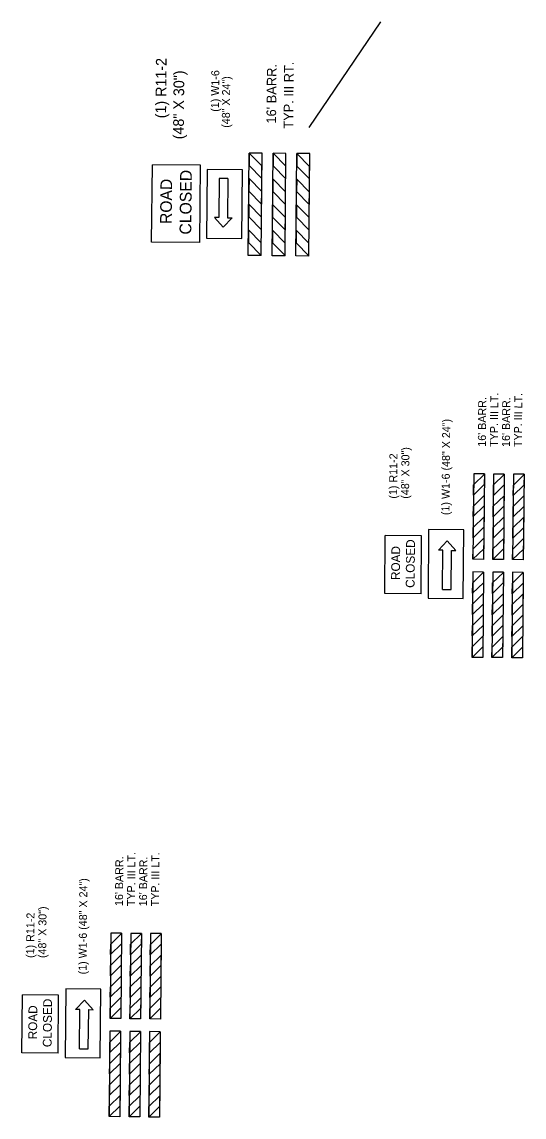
# Model space of a CAD drawing. Extents: x 1770269 to 1771406, y 724066 to 730989.
# Drawn here: x 1771030 to 1771406, y 727534 to 728355 of the extents above; entities that cross this region are included whole.
import ezdxf

# ---------------------------------------------------------------- set-up
doc = ezdxf.new("R2010")
doc.units = 0
doc.layers.add('R_Border PE', color=7, linetype='Continuous')
doc.layers.add('R_MOT', color=7, linetype='Continuous')

msp = doc.modelspace()

# ---------------------------------------------------------------- linework, layer by layer
at = {"layer": 'R_Border PE'}
msp.add_line((1771245.26, 728275.64), (1771299.11, 728354.86), dxfattribs=at)
at = {"layer": 'R_MOT'}
for p, q in [((1771199.65, 728179.7), (1771200.35, 728256.57)), ((1771210, 728256.49), (1771200.35, 728256.57)), ((1771209.3, 728179.61), (1771210, 728256.49)), ((1771209.97, 728256.43), (1771209.91, 728256.49)), ((1771217.54, 728179.54), (1771218.24, 728256.41)), ((1771227.86, 728256.32), (1771218.24, 728256.41)), ((1771227.86, 728256.32), (1771218.24, 728256.41)), ((1771227.16, 728179.45), (1771227.86, 728256.32)), ((1771235.38, 728179.37), (1771236.07, 728256.25)), ((1771245.7, 728256.16), (1771236.07, 728256.25)), ((1771245, 728179.29), (1771245.7, 728256.16)), ((1771127.17, 728189.81), (1771127.7, 728247.78)), ((1771163.91, 728247.45), (1771127.7, 728247.78)), ((1771163.38, 728189.49), (1771163.91, 728247.45)), ((1771177.86, 728237.53), (1771177.59, 728208.15)), ((1771184.4, 728237.47), (1771177.86, 728237.53)), ((1771184.4, 728237.47), (1771184.14, 728208.09)), ((1771177.59, 728208.15), (1771174.32, 728208.18)), ((1771180.8, 728200.94), (1771174.32, 728208.18)), ((1771187.41, 728208.06), (1771180.8, 728200.94)), ((1771184.14, 728208.09), (1771187.41, 728208.06)), ((1771163.38, 728189.49), (1771127.17, 728189.81)), ((1771209.3, 728179.61), (1771199.65, 728179.7)), ((1771227.16, 728179.45), (1771217.54, 728179.54)), ((1771245, 728179.29), (1771235.38, 728179.37)), ((1771368.62, 728016.03), (1771368.04, 727952)), ((1771376.66, 728015.96), (1771368.62, 728016.03)), ((1771376.66, 728015.96), (1771376.08, 727951.93)), ((1771383.53, 728015.9), (1771382.94, 727951.87)), ((1771391.54, 728015.82), (1771383.53, 728015.9)), ((1771391.54, 728015.82), (1771390.96, 727951.79)), ((1771398.38, 728015.76), (1771397.8, 727951.73)), ((1771406.4, 728015.69), (1771398.38, 728015.76)), ((1771406.4, 728015.69), (1771405.82, 727951.66)), ((1771301.97, 727926.34), (1771302.36, 727969.8)), ((1771329.5, 727969.55), (1771302.36, 727969.8)), ((1771329.11, 727926.1), (1771329.5, 727969.55)), ((1771342.2, 727958.76), (1771348.81, 727965.88)), ((1771348.81, 727965.88), (1771355.29, 727958.65)), ((1771345.48, 727958.74), (1771342.2, 727958.76)), ((1771345.21, 727929.35), (1771345.48, 727958.74)), ((1771351.75, 727929.29), (1771352.02, 727958.68)), ((1771352.02, 727958.68), (1771355.29, 727958.65)), ((1771376.08, 727951.93), (1771368.04, 727952)), ((1771376.06, 727951.98), (1771376.01, 727951.93)), ((1771390.96, 727951.79), (1771382.94, 727951.87)), ((1771390.96, 727951.79), (1771382.94, 727951.87)), ((1771405.82, 727951.66), (1771397.8, 727951.73)), ((1771367.96, 727942.5), (1771367.37, 727878.47)), ((1771375.99, 727942.43), (1771367.96, 727942.5)), ((1771375.99, 727942.43), (1771375.41, 727878.4)), ((1771382.86, 727942.37), (1771382.28, 727878.34)), ((1771390.87, 727942.3), (1771382.86, 727942.37)), ((1771390.87, 727942.3), (1771390.29, 727878.27)), ((1771397.71, 727942.23), (1771397.13, 727878.2)), ((1771405.73, 727942.16), (1771397.71, 727942.23)), ((1771405.73, 727942.16), (1771405.15, 727878.13)), ((1771329.11, 727926.1), (1771301.97, 727926.34)), ((1771345.21, 727929.35), (1771351.75, 727929.29)), ((1771375.41, 727878.4), (1771367.37, 727878.47)), ((1771375.39, 727878.45), (1771375.34, 727878.4)), ((1771390.29, 727878.27), (1771382.28, 727878.34)), ((1771390.29, 727878.27), (1771382.28, 727878.34)), ((1771405.15, 727878.13), (1771397.13, 727878.2)), ((1771096.55, 727671.69), (1771095.97, 727607.66)), ((1771104.59, 727671.62), (1771096.55, 727671.69)), ((1771104.59, 727671.62), (1771104.01, 727607.59)), ((1771111.45, 727671.55), (1771110.87, 727607.52)), ((1771119.47, 727671.48), (1771111.45, 727671.55)), ((1771119.47, 727671.48), (1771118.89, 727607.45)), ((1771126.31, 727671.42), (1771125.73, 727607.39)), ((1771134.32, 727671.35), (1771126.31, 727671.42)), ((1771134.32, 727671.35), (1771133.74, 727607.32)), ((1771029.89, 727582), (1771030.29, 727625.45)), ((1771057.43, 727625.21), (1771030.29, 727625.45)), ((1771057.03, 727581.76), (1771057.43, 727625.21)), ((1771070.13, 727614.42), (1771076.74, 727621.54)), ((1771076.74, 727621.54), (1771083.22, 727614.3)), ((1771073.4, 727614.39), (1771070.13, 727614.42)), ((1771073.13, 727585.01), (1771073.4, 727614.39)), ((1771079.68, 727584.95), (1771079.95, 727614.33)), ((1771079.95, 727614.33), (1771083.22, 727614.3)), ((1771104.01, 727607.59), (1771095.97, 727607.66)), ((1771103.98, 727607.63), (1771103.94, 727607.59)), ((1771118.89, 727607.45), (1771110.87, 727607.52)), ((1771118.89, 727607.45), (1771110.87, 727607.52)), ((1771133.74, 727607.32), (1771125.73, 727607.39)), ((1771095.88, 727598.16), (1771095.3, 727534.13)), ((1771103.92, 727598.09), (1771095.88, 727598.16)), ((1771103.92, 727598.09), (1771103.34, 727534.06)), ((1771110.78, 727598.03), (1771110.2, 727534)), ((1771118.8, 727597.95), (1771110.78, 727598.03)), ((1771118.8, 727597.95), (1771118.22, 727533.92)), ((1771125.64, 727597.89), (1771125.06, 727533.86)), ((1771133.66, 727597.82), (1771125.64, 727597.89)), ((1771133.66, 727597.82), (1771133.07, 727533.79)), ((1771057.03, 727581.76), (1771029.89, 727582)), ((1771073.13, 727585.01), (1771079.68, 727584.95)), ((1771103.34, 727534.06), (1771095.3, 727534.13)), ((1771103.32, 727534.11), (1771103.27, 727534.06)), ((1771118.22, 727533.92), (1771110.2, 727534)), ((1771118.22, 727533.92), (1771110.2, 727534)), ((1771133.07, 727533.79), (1771125.06, 727533.86))]:
    msp.add_line(p, q, dxfattribs=at)
for points in [[(1771200.35, 728256.57), (1771200.29, 728247.12), (1771209.8, 728237.44), (1771209.88, 728246.86)], [(1771218.24, 728256.41), (1771218.18, 728246.96), (1771227.69, 728237.28), (1771227.78, 728246.7)], [(1771236.07, 728256.25), (1771236.02, 728246.8), (1771245.52, 728237.12), (1771245.61, 728246.54)], [(1771194.76, 728192.42), (1771195.23, 728243.95), (1771168.88, 728244.19), (1771168.41, 728192.66)], [(1771200.17, 728237.36), (1771200.11, 728227.91), (1771209.62, 728218.23), (1771209.71, 728227.65)], [(1771218.06, 728237.2), (1771218.01, 728227.75), (1771227.52, 728218.07), (1771227.6, 728227.49)], [(1771235.9, 728237.04), (1771235.84, 728227.59), (1771245.35, 728217.91), (1771245.44, 728227.33)], [(1771200, 728218.16), (1771199.94, 728208.7), (1771209.45, 728199.02), (1771209.53, 728208.44)], [(1771217.89, 728217.99), (1771217.83, 728208.54), (1771227.34, 728198.86), (1771227.43, 728208.28)], [(1771235.73, 728217.83), (1771235.67, 728208.38), (1771245.18, 728198.7), (1771245.26, 728208.12)], [(1771199.82, 728198.95), (1771199.77, 728189.5), (1771209.27, 728179.81), (1771209.36, 728189.24)], [(1771217.72, 728198.78), (1771217.66, 728189.33), (1771227.17, 728179.65), (1771227.25, 728189.07)], [(1771235.55, 728198.62), (1771235.49, 728189.17), (1771245, 728179.49), (1771245.09, 728188.91)], [(1771368.48, 728000), (1771368.57, 728007.87), (1771376.64, 728015.79), (1771376.57, 728007.94)], [(1771383.38, 727999.86), (1771383.48, 728007.74), (1771391.54, 728015.66), (1771391.47, 728007.81)], [(1771398.24, 727999.73), (1771398.33, 728007.6), (1771406.4, 728015.52), (1771406.32, 728007.67)], [(1771368.33, 727984), (1771368.43, 727991.87), (1771376.49, 727999.79), (1771376.42, 727991.94)], [(1771383.24, 727983.87), (1771383.33, 727991.74), (1771391.4, 727999.66), (1771391.32, 727991.81)], [(1771398.09, 727983.73), (1771398.19, 727991.6), (1771406.25, 727999.52), (1771406.18, 727991.67)], [(1771368.19, 727968), (1771368.28, 727975.87), (1771376.35, 727983.79), (1771376.28, 727975.94)], [(1771383.09, 727967.87), (1771383.19, 727975.74), (1771391.25, 727983.66), (1771391.18, 727975.81)], [(1771397.95, 727967.73), (1771398.04, 727975.6), (1771406.11, 727983.52), (1771406.03, 727975.67)], [(1771334.85, 727974.41), (1771334.38, 727922.88), (1771360.73, 727922.64), (1771361.2, 727974.17)], [(1771368.04, 727952), (1771368.14, 727959.87), (1771376.2, 727967.79), (1771376.13, 727959.94)], [(1771382.94, 727951.87), (1771383.04, 727959.74), (1771391.1, 727967.66), (1771391.03, 727959.81)], [(1771397.8, 727951.73), (1771397.9, 727959.6), (1771405.96, 727967.52), (1771405.89, 727959.67)], [(1771367.81, 727926.47), (1771367.91, 727934.34), (1771375.97, 727942.26), (1771375.9, 727934.42)], [(1771382.71, 727926.34), (1771382.81, 727934.21), (1771390.87, 727942.13), (1771390.8, 727934.28)], [(1771397.57, 727926.2), (1771397.66, 727934.07), (1771405.73, 727941.99), (1771405.66, 727934.15)], [(1771367.66, 727910.47), (1771367.76, 727918.34), (1771375.82, 727926.26), (1771375.75, 727918.42)], [(1771382.57, 727910.34), (1771382.66, 727918.21), (1771390.73, 727926.13), (1771390.66, 727918.28)], [(1771397.42, 727910.2), (1771397.52, 727918.07), (1771405.58, 727925.99), (1771405.51, 727918.15)], [(1771367.52, 727894.47), (1771367.61, 727902.35), (1771375.68, 727910.26), (1771375.61, 727902.42)], [(1771382.42, 727894.34), (1771382.52, 727902.21), (1771390.58, 727910.13), (1771390.51, 727902.28)], [(1771397.28, 727894.2), (1771397.37, 727902.07), (1771405.44, 727909.99), (1771405.37, 727902.15)], [(1771367.37, 727878.47), (1771367.47, 727886.35), (1771375.53, 727894.26), (1771375.46, 727886.42)], [(1771382.28, 727878.34), (1771382.37, 727886.21), (1771390.44, 727894.13), (1771390.37, 727886.28)], [(1771397.13, 727878.2), (1771397.23, 727886.08), (1771405.29, 727893.99), (1771405.22, 727886.15)], [(1771096.4, 727655.66), (1771096.5, 727663.53), (1771104.56, 727671.45), (1771104.49, 727663.6)], [(1771111.31, 727655.52), (1771111.4, 727663.39), (1771119.47, 727671.31), (1771119.4, 727663.47)], [(1771126.16, 727655.39), (1771126.26, 727663.26), (1771134.32, 727671.18), (1771134.25, 727663.33)], [(1771096.26, 727639.66), (1771096.35, 727647.53), (1771104.42, 727655.45), (1771104.35, 727647.6)], [(1771111.16, 727639.52), (1771111.26, 727647.39), (1771119.32, 727655.31), (1771119.25, 727647.47)], [(1771126.02, 727639.39), (1771126.11, 727647.26), (1771134.18, 727655.18), (1771134.11, 727647.33)], [(1771096.11, 727623.66), (1771096.21, 727631.53), (1771104.27, 727639.45), (1771104.2, 727631.6)], [(1771111.02, 727623.52), (1771111.11, 727631.39), (1771119.18, 727639.31), (1771119.1, 727631.47)], [(1771125.87, 727623.39), (1771125.97, 727631.26), (1771134.03, 727639.18), (1771133.96, 727631.33)], [(1771062.78, 727630.06), (1771062.31, 727578.53), (1771088.66, 727578.3), (1771089.13, 727629.82)], [(1771095.97, 727607.66), (1771096.06, 727615.53), (1771104.13, 727623.45), (1771104.06, 727615.6)], [(1771110.87, 727607.52), (1771110.97, 727615.4), (1771119.03, 727623.31), (1771118.96, 727615.47)], [(1771125.73, 727607.39), (1771125.82, 727615.26), (1771133.89, 727623.18), (1771133.81, 727615.33)], [(1771095.74, 727582.13), (1771095.83, 727590), (1771103.9, 727597.92), (1771103.82, 727590.07)], [(1771110.64, 727581.99), (1771110.73, 727589.87), (1771118.8, 727597.79), (1771118.73, 727589.94)], [(1771125.49, 727581.86), (1771125.59, 727589.73), (1771133.65, 727597.65), (1771133.58, 727589.8)], [(1771095.59, 727566.13), (1771095.69, 727574), (1771103.75, 727581.92), (1771103.68, 727574.07)], [(1771110.49, 727566), (1771110.59, 727573.87), (1771118.65, 727581.79), (1771118.58, 727573.94)], [(1771125.35, 727565.86), (1771125.44, 727573.73), (1771133.51, 727581.65), (1771133.44, 727573.8)], [(1771095.44, 727550.13), (1771095.54, 727558), (1771103.6, 727565.92), (1771103.53, 727558.07)], [(1771110.35, 727550), (1771110.44, 727557.87), (1771118.51, 727565.79), (1771118.44, 727557.94)], [(1771125.2, 727549.86), (1771125.3, 727557.73), (1771133.36, 727565.65), (1771133.29, 727557.8)], [(1771095.3, 727534.13), (1771095.39, 727542), (1771103.46, 727549.92), (1771103.39, 727542.08)], [(1771110.2, 727534), (1771110.3, 727541.87), (1771118.36, 727549.79), (1771118.29, 727541.94)], [(1771125.06, 727533.86), (1771125.15, 727541.73), (1771133.22, 727549.65), (1771133.15, 727541.8)]]:
    msp.add_lwpolyline(points, close=True, dxfattribs=at)

# ---------------------------------------------------------------- texts
for s, height, p in [('(1) R11-2', 8.004, (1771137.98, 728282.57)), ('(48" X 30")', 8.004, (1771151.22, 728266.82)), ('(1) W1-6', 6, (1771177.6, 728287.46)), ("16' BARR.", 7.204, (1771220.42, 728278.58)), ('TYP. III RT.', 7.2036, (1771233.25, 728274.72)), ('(48" X 24")', 6, (1771185.75, 728275.46)), ('CLOSED', 8.817, (1771156.89, 728195.4)), ('ROAD', 8.774, (1771142.27, 728203.31)), ("16' BARR.", 6, (1771377.73, 728036.36)), ('TYP. III LT.', 6, (1771386.73, 728036.28)), ("16' BARR.", 6, (1771395.73, 728036.19)), ('TYP. III LT.', 6, (1771404.73, 728036.11)), ('(1) W1-6 (48" X 24")', 6, (1771350.41, 727985.09)), ('(1) R11-2', 6, (1771311.12, 727997.44)), ('(48" X 30")', 6, (1771320.12, 727997.36)), ('CLOSED', 6.61, (1771324.25, 727930.53)), ('ROAD', 6.577, (1771313.29, 727936.46)), ("16' BARR.", 6, (1771105.66, 727692.01)), ('TYP. III LT.', 6, (1771114.66, 727691.93)), ("16' BARR.", 6, (1771123.66, 727691.85)), ('TYP. III LT.', 6, (1771132.66, 727691.77)), ('(1) W1-6 (48" X 24")', 6, (1771078.33, 727640.75)), ('(1) R11-2', 6, (1771039.04, 727653.09)), ('(48" X 30")', 6, (1771048.04, 727653.01)), ('CLOSED', 6.61, (1771052.17, 727586.19)), ('ROAD', 6.577, (1771041.21, 727592.12))]:
    msp.add_text(s, height=height, rotation=89.47959, dxfattribs=at).set_placement(p)

doc.saveas('drawing.dxf')
